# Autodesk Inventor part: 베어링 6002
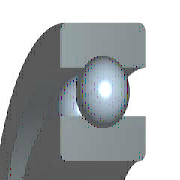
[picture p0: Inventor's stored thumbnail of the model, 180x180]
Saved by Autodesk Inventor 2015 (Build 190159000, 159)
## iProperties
IsCustomPart: 0
Created: 2015-10
Part Number: 베어링 6002
Material: Steel, Mild
Description: 깊은 그루브 볼 베어링
Document SubType Name: Modeling
Standard: KS B 2023
Designer: mdu
Standards Organization: KS
Language: ko-KR
Size Designation: 6002 - 15 x 32 x 9
Categories: <MemberInstance><Categories><Category DisplayName="샤프트 부품" InternalName="7f7aeb1f-a693-4053-b835-cee3144e0d98" Mnemonic="SHFT"><Category DisplayName="베어링" Inter
Density: 1 g/cm^3
Appearance: Steel
Author: mdu
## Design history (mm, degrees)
revolve "본체" stored, may be unused: angle "d6" = 90 deg
revolve "볼" stored, may be unused: angle "d7" = 90 deg
pattern_circular "IDS_ARRAYBALL[SIMPL:T]" dims angle "d3" = 360 deg
body "Solid1"
sketch "스케치" dims "d0" = 4.42 (= -0.26 x WD + 0.26 x BD)
  geometry: L1 (2.29, 11.75)-(6.71, 11.75); L2 (4.5, 11.75)-(4.5, 9.54); L3 (4.5, 11.75)-(4.5, 13.96); L4 (2.858, 10.271)-(0, 10.271); L5 (0, 7.5)-(9, 7.5); L6 (2.858, 13.229)-(0, 13.229); L7 (0, 16)-(9, 16); L8 (9, 7.5)-(9, 10.271); L9 (6.142, 10.271)-(9, 10.271); L10 (6.142, 13.229)-(9, 13.229); L11 (9, 16)-(9, 13.229); L12 (-1.4, 0)-(8.4, 0) reference; L13 (0, -0.3)-(0, 5.3) reference
  constraints: 22 end point, 4 point on line, 2 collinear, 2 perpendicular, 2 symmetric about line, 1 midpoint, 1 parallel, 14 other
  dimensions: "d9" = 15 diameter of L5 L12 (= WD); "d11" = 32 diameter of L7 L12 (= BD); "d12" = 9 distance between parallel lines of L8 L13 (= KB); "d13" = 20.542 diameter of L9 L12 (= 0.326 x BD + 0.674 x WD)
fillet "모깎기1" dims "d1" = 0.3 (= KRS)
other parameters: "WD" = 15 [user parameter; used in 5 equation terms], "BD" = 32 [user parameter; used in 5 equation terms], "KB" = 9 [user parameter; used in 1 equation term], "KRS" = 0.3 [user parameter; used in 1 equation term], "d4" = 0, "d5" = 0, "d8" = 0, "d14" = 0, "d15" = 0, "BBA" = 0 [user parameter], "BC0" = 2850000 [user parameter], "BC" = 5590000 [user parameter], "BR" = 16 (= 0.5 x BD) [user parameter], "WR" = 7.5 (= 0.5 x WD) [user parameter]
